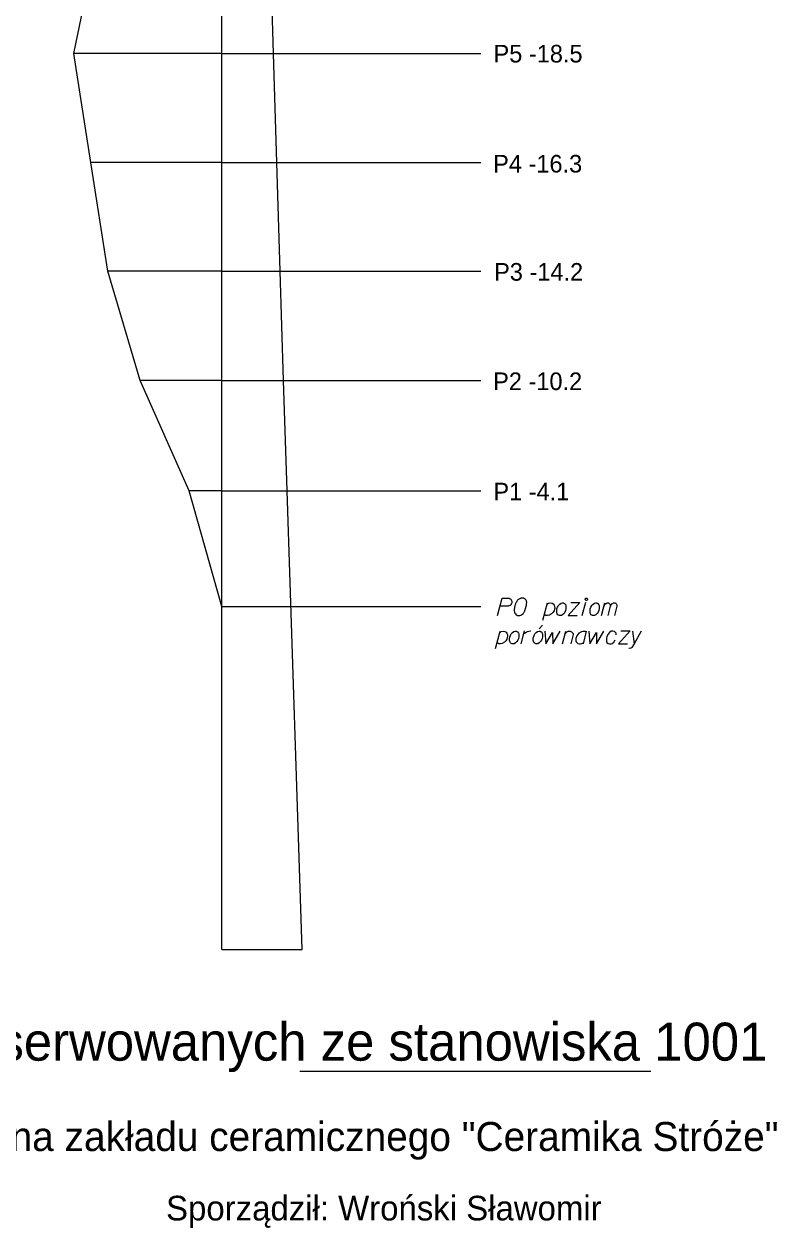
# Model space of a CAD drawing. Extents: x 138 to 6653, y -177 to 1520.
# Drawn here: x 207.43 to 216.83, y 84.49 to 99.53 of the extents above; entities that cross this region are included whole.
import ezdxf

# ---------------------------------------------------------------- set-up
doc = ezdxf.new("R2010")
doc.units = 0
for name, color, linetype in [('Opisy', 7, 'Continuous'), ('Standart wykresów', 7, 'Continuous'), ('Wykresy 4 maj 2008', 7, 'Continuous')]:
    doc.layers.add(name, color=color, linetype=linetype)

msp = doc.modelspace()

# ---------------------------------------------------------------- linework, layer by layer
at = {"layer": 'Opisy'}
msp.add_line((210.874, 86.444), (215.259, 86.444), dxfattribs=at)
at = {"layer": 'Standart wykresów'}
for p, q in [((209.897, 87.967), (209.897, 108.051)), ((210.544, 99.158), (210.5, 100.549)), ((209.897, 99.158), (213.134, 99.158)), ((210.587, 97.799), (210.544, 99.158)), ((209.897, 97.799), (213.134, 97.799)), ((210.629, 96.441), (210.587, 97.799)), ((209.897, 96.441), (213.134, 96.441)), ((210.671, 95.074), (210.629, 96.441)), ((209.897, 95.074), (213.134, 95.074)), ((210.716, 93.698), (210.671, 95.074)), ((209.897, 93.698), (209.49, 93.698)), ((209.897, 93.698), (213.134, 93.698)), ((210.904, 87.967), (210.716, 93.698)), ((209.897, 92.253), (213.134, 92.253)), ((209.897, 87.967), (210.904, 87.967))]:
    msp.add_line(p, q, dxfattribs=at)
for points in [[(213.341, 92.137), (213.399, 92.357), (213.474, 92.357), (213.484, 92.355), (213.489, 92.354), (213.5, 92.348), (213.507, 92.343), (213.512, 92.336), (213.517, 92.328), (213.521, 92.316), (213.522, 92.305), (213.521, 92.296), (213.519, 92.29), (213.515, 92.283), (213.512, 92.277), (213.507, 92.271), (213.5, 92.265), (213.495, 92.262), (213.486, 92.258), (213.477, 92.257), (213.373, 92.257)], [(213.656, 92.357), (213.652, 92.357), (213.642, 92.355), (213.635, 92.354), (213.63, 92.352), (213.621, 92.348), (213.611, 92.343), (213.602, 92.338), (213.593, 92.331), (213.588, 92.324), (213.583, 92.316), (213.578, 92.307), (213.573, 92.296), (213.569, 92.29), (213.566, 92.279), (213.561, 92.262), (213.555, 92.236), (213.552, 92.215), (213.552, 92.196), (213.554, 92.182), (213.561, 92.167), (213.566, 92.158), (213.574, 92.148), (213.585, 92.141), (213.59, 92.139), (213.6, 92.137), (213.609, 92.137), (213.623, 92.139), (213.635, 92.142), (213.644, 92.148), (213.656, 92.156), (213.661, 92.161), (213.668, 92.168), (213.673, 92.175), (213.677, 92.18), (213.68, 92.189), (213.682, 92.193), (213.685, 92.201), (213.689, 92.212), (213.692, 92.222), (213.694, 92.229), (213.696, 92.234), (213.697, 92.241), (213.701, 92.257), (213.703, 92.265), (213.704, 92.274), (213.706, 92.286), (213.708, 92.302), (213.708, 92.307), (213.706, 92.314), (213.704, 92.321), (213.699, 92.331), (213.694, 92.338), (213.689, 92.343), (213.682, 92.348), (213.675, 92.352), (213.67, 92.354), (213.664, 92.355), (213.656, 92.357)], [(214.449, 92.357), (214.458, 92.357), (214.463, 92.354), (214.468, 92.347), (214.468, 92.338), (214.463, 92.331), (214.458, 92.328), (214.449, 92.328), (214.444, 92.331), (214.439, 92.338), (214.439, 92.347), (214.444, 92.354), (214.449, 92.357)], [(213.907, 92.08), (213.966, 92.296)], [(213.961, 92.277), (213.978, 92.291), (214.004, 92.296), (214.025, 92.293), (214.039, 92.283), (214.049, 92.269), (214.056, 92.25), (214.058, 92.232), (214.054, 92.217), (214.049, 92.198), (214.035, 92.177), (214.018, 92.158), (213.992, 92.141), (213.969, 92.137), (213.948, 92.139), (213.926, 92.151)], [(214.155, 92.296), (214.167, 92.296), (214.181, 92.29), (214.194, 92.271), (214.196, 92.262), (214.198, 92.253), (214.198, 92.246), (214.198, 92.22), (214.193, 92.203), (214.184, 92.182), (214.174, 92.165), (214.156, 92.149), (214.141, 92.137), (214.115, 92.137), (214.104, 92.141), (214.094, 92.149), (214.089, 92.158), (214.082, 92.179), (214.082, 92.21), (214.085, 92.22), (214.092, 92.243), (214.099, 92.255), (214.103, 92.262), (214.12, 92.281), (214.137, 92.291), (214.155, 92.296)], [(214.259, 92.3), (214.371, 92.3), (214.227, 92.137), (214.338, 92.137)], [(214.401, 92.137), (214.446, 92.305)], [(214.57, 92.296), (214.582, 92.296), (214.596, 92.29), (214.61, 92.271), (214.612, 92.262), (214.614, 92.253), (214.614, 92.246), (214.614, 92.22), (214.608, 92.203), (214.6, 92.182), (214.589, 92.165), (214.572, 92.149), (214.556, 92.137), (214.531, 92.137), (214.52, 92.141), (214.51, 92.149), (214.505, 92.158), (214.498, 92.179), (214.498, 92.21), (214.501, 92.22), (214.508, 92.243), (214.515, 92.255), (214.518, 92.262), (214.536, 92.281), (214.553, 92.291), (214.57, 92.296)], [(214.643, 92.137), (214.683, 92.295)], [(214.673, 92.253), (214.681, 92.272), (214.69, 92.283), (214.7, 92.29), (214.711, 92.295), (214.718, 92.298), (214.728, 92.298), (214.731, 92.296), (214.738, 92.29), (214.745, 92.281), (214.75, 92.265), (214.752, 92.257), (214.761, 92.272), (214.771, 92.283), (214.782, 92.29), (214.792, 92.295), (214.801, 92.298), (214.809, 92.298), (214.816, 92.296), (214.822, 92.29), (214.827, 92.281), (214.832, 92.265), (214.834, 92.257), (214.804, 92.137)], [(214.723, 92.137), (214.752, 92.257)], [(213.318, 91.727), (213.376, 91.943)], [(213.371, 91.924), (213.389, 91.938), (213.415, 91.943), (213.435, 91.94), (213.449, 91.929), (213.46, 91.916), (213.467, 91.897), (213.468, 91.879), (213.465, 91.864), (213.46, 91.845), (213.446, 91.824), (213.428, 91.805), (213.402, 91.787), (213.38, 91.784), (213.359, 91.786), (213.337, 91.798)], [(213.565, 91.943), (213.577, 91.943), (213.591, 91.936), (213.605, 91.917), (213.607, 91.909), (213.609, 91.9), (213.609, 91.893), (213.609, 91.867), (213.603, 91.85), (213.595, 91.829), (213.584, 91.812), (213.567, 91.796), (213.551, 91.784), (213.525, 91.784), (213.515, 91.787), (213.505, 91.796), (213.499, 91.805), (213.492, 91.825), (213.492, 91.857), (213.496, 91.867), (213.503, 91.89), (213.51, 91.902), (213.513, 91.909), (213.531, 91.928), (213.548, 91.938), (213.565, 91.943)], [(213.638, 91.784), (213.681, 91.948)], [(213.671, 91.909), (213.68, 91.916), (213.699, 91.929), (213.719, 91.938), (213.735, 91.943), (213.759, 91.948)], [(213.861, 91.943), (213.874, 91.943), (213.887, 91.936), (213.901, 91.917), (213.903, 91.909), (213.905, 91.9), (213.905, 91.893), (213.905, 91.867), (213.9, 91.85), (213.891, 91.829), (213.88, 91.812), (213.863, 91.796), (213.848, 91.784), (213.822, 91.784), (213.811, 91.787), (213.801, 91.796), (213.796, 91.805), (213.789, 91.825), (213.789, 91.857), (213.792, 91.867), (213.799, 91.89), (213.806, 91.902), (213.809, 91.909), (213.827, 91.928), (213.844, 91.938), (213.861, 91.943)], [(213.905, 92.02), (213.861, 91.971)], [(213.934, 91.942), (213.948, 91.784), (214.031, 91.928), (214.033, 91.784), (214.125, 91.945)], [(214.154, 91.784), (214.197, 91.943)], [(214.187, 91.905), (214.192, 91.914), (214.199, 91.924), (214.204, 91.929), (214.211, 91.936), (214.218, 91.94), (214.227, 91.943), (214.236, 91.945), (214.243, 91.945), (214.251, 91.943), (214.258, 91.94), (214.265, 91.936), (214.272, 91.931), (214.279, 91.924), (214.282, 91.919), (214.286, 91.912), (214.289, 91.903), (214.258, 91.784)], [(214.449, 91.929), (214.437, 91.938), (214.407, 91.938), (214.39, 91.935), (214.359, 91.917), (214.333, 91.886), (214.32, 91.853), (214.319, 91.836), (214.32, 91.822), (214.326, 91.81), (214.336, 91.796), (214.348, 91.787), (214.367, 91.784), (214.381, 91.786), (214.395, 91.787), (214.414, 91.798)], [(214.452, 91.943), (214.411, 91.784)], [(214.482, 91.942), (214.495, 91.784), (214.579, 91.928), (214.58, 91.784), (214.672, 91.945)], [(214.825, 91.897), (214.823, 91.917), (214.814, 91.931), (214.804, 91.938), (214.783, 91.942), (214.764, 91.942), (214.74, 91.926), (214.721, 91.9), (214.707, 91.874), (214.702, 91.855), (214.702, 91.825), (214.703, 91.815), (214.71, 91.801), (214.726, 91.787), (214.743, 91.784), (214.762, 91.786), (214.773, 91.789), (214.795, 91.805), (214.812, 91.834)], [(214.885, 91.947), (214.998, 91.947), (214.854, 91.784), (214.965, 91.784)], [(215.138, 91.945), (215.05, 91.784), (215.022, 91.737), (215.015, 91.734), (215.006, 91.73), (214.989, 91.727), (214.982, 91.727)], [(215.027, 91.943), (215.05, 91.784)]]:
    msp.add_lwpolyline(points, dxfattribs=at)
at = {"layer": 'Wykresy 4 maj 2008'}
for p, q in [((209.897, 99.158), (208.05, 99.158)), ((209.897, 97.799), (208.263, 97.799)), ((209.897, 96.441), (208.475, 96.441)), ((209.897, 95.074), (208.88, 95.074))]:
    msp.add_line(p, q, dxfattribs=at)
msp.add_lwpolyline([(209.897, 92.253), (209.49, 93.698), (208.88, 95.074), (208.475, 96.441), (208.263, 97.799), (208.05, 99.158), (208.338, 100.549), (208.516, 101.951), (208.223, 102.945), (208.116, 103.925), (208.024, 104.384), (207.528, 104.901), (207.135, 105.369), (206.14, 105.937), (205.674, 106.463), (205.36, 106.65), (202.317, 107.348), (200.558, 107.711), (198.761, 107.967)], dxfattribs=at)

# ---------------------------------------------------------------- texts
at = {"layer": 'Opisy'}
for s, height, p in [('Wykres wychyleń osi komina obserwowanych ze stanowiska 1001', 0.47516, (198.103, 86.577)), ('Badanie pionowości i prostoliniowości komina zakładu ceramicznego "Ceramika Stróże"', 0.36281, (197.983, 85.448)), ('Sporządził: Wroński Sławomir', 0.30766, (209.202, 84.581))]:
    msp.add_text(s, height=height, dxfattribs=at).set_placement(p)
at = {"layer": 'Wykresy 4 maj 2008'}
for s, p in [('P5 -18.5', (213.293, 99.048)), ('P4 -16.3', (213.288, 97.673)), ('P3 -14.2', (213.3, 96.322)), ('P2 -10.2', (213.288, 94.955)), ('P1 -4.1', (213.291, 93.577))]:
    msp.add_text(s, height=0.22, dxfattribs=at).set_placement(p)

doc.saveas('drawing.dxf')
